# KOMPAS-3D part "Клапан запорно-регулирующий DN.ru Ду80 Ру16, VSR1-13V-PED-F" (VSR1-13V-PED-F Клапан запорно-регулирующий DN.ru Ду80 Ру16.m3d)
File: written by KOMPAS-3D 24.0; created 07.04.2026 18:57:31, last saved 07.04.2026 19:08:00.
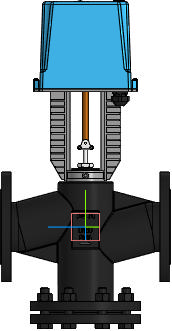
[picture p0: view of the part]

Document properties: Автор: R2D2; Полное имя файла: E:\Работа\Зайцев\Солянка\VSR1-13V-PED-F Клапан запорно-регулирующий DN.ru\DN80\VSR1-13V-PED-F Клапан запорно-регулирующий DN.ru Ду80 Ру16.m3d

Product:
- Part/product: Клапан запорно-регулирующий DN.ru Ду80 Ру16  | designation VSR1-13V-PED-F
    Масса: 27.5
    Раздел спецификации: Прочие изделия
    Примечание: D090-02893

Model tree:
1. Операция без истории:1  (labels: SHAPEOBJECT3D_ATTR_BUTT)

Expressions: VSR1-13V-PED-F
